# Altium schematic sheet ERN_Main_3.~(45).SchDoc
size A; SheetNumber: 3; SheetTotal: 4; SPICEModelCacheXVWYUVSQ: <root> / <DocumentId>XVWYUVSQ</DocumentId> / <CacheFrame Number="0"> / <Model Name="irf1010" Kind="CKT"> / <Text>*IRF1010 MCE 4-2-96 / *55V  75A .014 ohm HEXFET pkg:TO-220 2,1,3 / .SUBCKT IRF1010  10 20 40 40 / M1   1  2  3  3  DMOS L=1U W=1U / RD  10  1  5.65M / RS  30  3  1.35M / RG  20  2  12.1 / CGS  2  3  2.15N / EGD 12  0  2  1  1 / VFB 14  0  0 / FFB  2  1  VFB  1 / CGD 13 14  4.49N / R1  13  0  1 / D1  12 13  DLIM / DDG 15 14  DCGD / R2  12 15  1 / D2  15  0  DLIM / DSD  3 10  DSUB / LS  30 40  7.5N / .MODEL DMOS NMOS (LEVEL=3 THETA=60M VMAX=114K ETA=2M VTO=3 KP=19.4) / .MODEL DCGD D (CJO=4.49N VJ=.6 M=.68) / .MODEL DSUB D (IS=311N N=1.5 RS=8.67M BV=55 CJO=4.08N VJ=.8 M=.42 TT=100N) / .MODEL DLIM D (IS=100U) / .ENDS IRF1010</Text> / </Model> / <Model Name="1n4148" Kind="MDL"> / <Text>.model 1N4148  D(Is=0.1p Rs=16 CJO=2p Tt=12n Bv=100 Ibv=0.1p)</Text> / </Model> / <Model Name="npn" Kind="MDL"> / <Text>*Default NPN BJT / *NPN Trans Pinout: C,B,E / .MODEL NPN NPN()</Text> / </Model> / </CacheFrame> / </root>
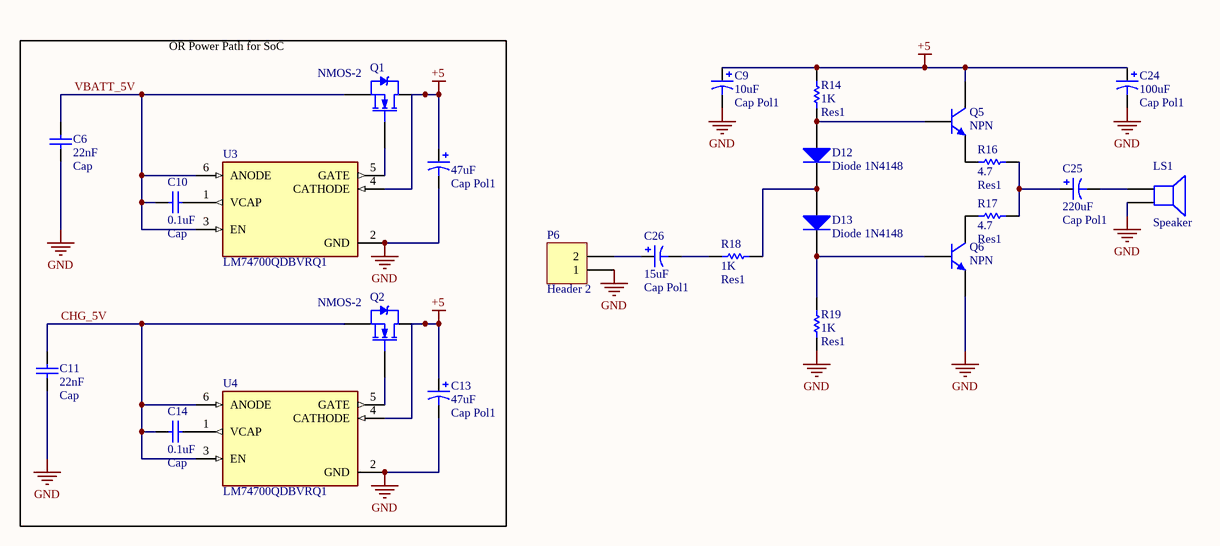
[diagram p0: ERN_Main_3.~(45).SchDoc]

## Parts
?  Cap Pol1  value 47uF  [RB7.6-15]
C6  Cap  value 22nF  [RAD-0.3]
C9  Cap Pol1  value 10uF  [RB7.6-15]
C10  Cap  value 0.1uF  [RAD-0.3]
C11  Cap  value 22nF  [RAD-0.3]
C13  Cap Pol1  value 47uF  [RB7.6-15]
C14  Cap  value 0.1uF  [RAD-0.3]
C24  Cap Pol1  value 100uF  [RB7.6-15]
C25  Cap Pol1  value 220uF  [RB7.6-15]
C26  Cap Pol1  value 15uF  [RB7.6-15]
D12  Diode 1N4148  [DO-35]
D13  Diode 1N4148  [DO-35]
LS1  Speaker  [PIN2]
P6  Header 2  [HDR1X2]
Q1  NMOS-2  [TO-220AB]
Q2  NMOS-2  [TO-220AB]
Q5  NPN  [TO-226-AA]
Q6  NPN  [TO-226-AA]
R14  Res1  value 1K  [AXIAL-0.3]
R16  Res1  value 4.7  [AXIAL-0.3]
R17  Res1  value 4.7  [AXIAL-0.3]
R18  Res1  value 1K  [AXIAL-0.3]
R19  Res1  value 1K  [AXIAL-0.3]
U3  LM74700QDBVRQ1  [SOT95P280X145-6N]
U4  LM74700QDBVRQ1  [SOT95P280X145-6N]

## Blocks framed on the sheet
OR Power Path for SoC: ? C6 C10 C11 C13 C14 Q1 Q2 U3 U4

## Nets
+5: ?.1 C9.1 C13.1 C24.1 Q1.2(D) Q2.2(D) Q5.1(C) R14.2 U3.4(CATHODE) U4.4(CATHODE)
GND: ?.2 C6.1 C9.2 C11.1 C13.2 C24.2 LS1.2 P6.1 Q6.3(E) R19.1 U3.2(GND) U4.2(GND)
CHG_5V: C11.2 C14.2 Q2.3(S) U4.3(EN) U4.6(ANODE)
VBATT_5V: C6.2 C10.2 Q1.3(S) U3.3(EN) U3.6(ANODE)
NetC10_1: C10.1 U3.1(VCAP)
NetC14_1: C14.1 U4.1(VCAP)
NetC25_1: C25.1 R16.2 R17.2
NetC25_2: C25.2 LS1.1
NetC26_1: C26.1 P6.2
NetC26_2: C26.2 R18.1
NetD12_1: D12.1(A) Q5.2(B) R14.1
NetD12_2: D12.2(K) D13.1(A) R18.2
NetD13_2: D13.2(K) Q6.2(B) R19.2
NetQ1_1: Q1.1(G) U3.5(GATE)
NetQ2_1: Q2.1(G) U4.5(GATE)
NetQ5_3: Q5.3(E) R16.1
NetQ6_1: Q6.1(C) R17.1

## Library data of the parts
? C9 C13 C24-C26 = Cap Pol1: Polarized Capacitor (Radial)
C6 C10 C11 C14 = Cap: Capacitor
D12 D13 = Diode 1N4148: High Conductance Fast Diode
LS1 = Speaker: Loudspeaker
P6 = Header 2: Header, 2-Pin
Q1 Q2 = NMOS-2: N-Channel Power MOSFET; Note: Pin 2 is electrically connected to pin 4.
Q5 Q6 = NPN: NPN Bipolar Transistor
R14 R16-R19 = Res1: Resistor
U3 U4 = LM74700QDBVRQ1: 3.2-V to 65-V, 80-uA IQ automotive ideal diode controller; MF: Texas Instruments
